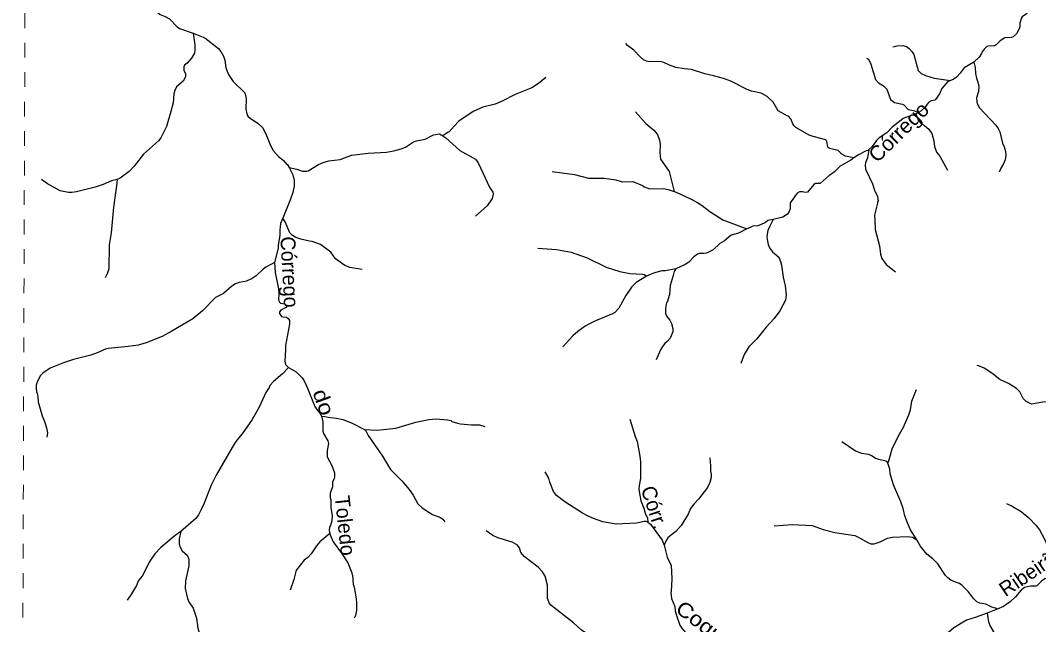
# Model space of a CAD drawing. Extents: x 551.6 to 577.6, y 7567 to 7594.7.
# Drawn here: x 551.65 to 558.55, y 7583.85 to 7587.95 of the extents above; entities that cross this region are included whole.
import ezdxf
from ezdxf.enums import TextEntityAlignment as Align

# ---------------------------------------------------------------- set-up
doc = ezdxf.new("R2010")
doc.units = 0
doc.header["$LTSCALE"] = 0.04
doc.linetypes.add('SHORT_DASHED', pattern=[2.7, 1.5, -1.2])
doc.layers.add('53', color=7, linetype='SHORT_DASHED', lineweight=13)
doc.layers.add('7', color=7, linetype='Continuous', lineweight=25)
doc.layers.add('61', color=7, linetype='Continuous')

msp = doc.modelspace()

# ---------------------------------------------------------------- linework, layer by layer
at = {"layer": '53'}
msp.add_lwpolyline([(551.6503, 7578.541), (551.6589, 7581.176), (551.6615, 7581.9586), (551.6634, 7582.5573), (551.6645, 7582.8996), (551.6852, 7589.2613), (551.6863, 7589.5882), (551.6896, 7590.6141), (551.6917, 7591.2598), (551.6958, 7592.5139), (551.6971, 7592.9033), (551.701, 7594.113), (551.703, 7594.7296), (552.7903, 7594.7256), (553.4424, 7594.7233), (554.6279, 7594.7189), (556.5859, 7594.7118), (557.3702, 7594.7089), (557.7663, 7594.7075), (559.9893, 7594.6994)], dxfattribs=at)
at = {"layer": '7'}
for points in [[(552.32, 7588.3987), (552.3168, 7588.3536), (552.3265, 7588.3198), (552.3466, 7588.2763), (552.3828, 7588.2385), (552.4367, 7588.2063), (552.4874, 7588.1652), (552.4939, 7588.1492), (552.5019, 7588.0928), (552.5075, 7588.0816), (552.5679, 7588.0172), (552.5969, 7587.9906), (552.6323, 7587.9777), (552.6605, 7587.9624), (552.712, 7587.9069), (552.7289, 7587.8964), (552.8218, 7587.8654)], [(558.4947, 7588.043), (558.4711, 7587.9954), (558.4397, 7587.9745), (558.4365, 7587.9689), (558.4252, 7587.9335), (558.4252, 7587.9077), (558.4212, 7587.8949), (558.4019, 7587.8602), (558.3802, 7587.8393), (558.3673, 7587.8353), (558.3222, 7587.8337), (558.2917, 7587.8119), (558.2651, 7587.7846), (558.253, 7587.7781), (558.245, 7587.7757), (558.2208, 7587.7789), (558.2023, 7587.7733), (558.183, 7587.7564), (558.1693, 7587.7387), (558.1661, 7587.7266), (558.1484, 7587.7017), (558.1123, 7587.6688)], [(552.8218, 7587.8654), (552.8335, 7587.7854), (552.8335, 7587.7516), (552.8295, 7587.7291), (552.811, 7587.6953), (552.782, 7587.6614), (552.7635, 7587.647), (552.7594, 7587.6373), (552.7578, 7587.6132), (552.7691, 7587.5882), (552.7691, 7587.5713), (552.7651, 7587.5601), (552.753, 7587.5399), (552.7096, 7587.5013), (552.6967, 7587.4747), (552.691, 7587.4538), (552.6854, 7587.3927), (552.6709, 7587.3331), (552.6403, 7587.2317), (552.6017, 7587.1544), (552.5872, 7587.1335), (552.4858, 7587.0434)], [(552.8218, 7587.8654), (552.9003, 7587.8329), (552.9928, 7587.7613), (553.0097, 7587.7403), (553.0283, 7587.7097), (553.0363, 7587.6808)], [(556.7118, 7587.4345), (556.6724, 7587.457), (556.6064, 7587.4723), (556.5774, 7587.4836), (556.4656, 7587.5399), (556.4165, 7587.5568), (556.3489, 7587.5761), (556.2893, 7587.589), (556.2, 7587.618), (556.1493, 7587.622), (556.093, 7587.6325), (556.0511, 7587.647), (556.0125, 7587.6663), (555.9932, 7587.6711), (555.961, 7587.6735), (555.9159, 7587.6703), (555.8934, 7587.6743), (555.8732, 7587.6848), (555.8507, 7587.7033), (555.8088, 7587.7492), (555.7654, 7587.7814), (555.7541, 7587.7942)], [(557.5633, 7587.7709), (557.5915, 7587.7798), (557.6317, 7587.7814), (557.6559, 7587.7741), (557.6744, 7587.7596), (557.6929, 7587.7403), (557.7058, 7587.721), (557.7363, 7587.6124), (557.7557, 7587.5906), (557.7863, 7587.5777), (557.8442, 7587.56), (557.955, 7587.5435)], [(553.0363, 7587.6808), (553.0435, 7587.6293), (553.0605, 7587.5842), (553.0935, 7587.5359), (553.1723, 7587.4603), (553.1812, 7587.4216), (553.178, 7587.3492), (553.1844, 7587.3178), (553.1932, 7587.3025), (553.2102, 7587.2856), (553.26, 7587.2542), (553.2906, 7587.2236), (553.3148, 7587.1818), (553.3453, 7587.1029), (553.3639, 7587.0675), (553.4009, 7587.0273), (553.4347, 7587.0007), (553.4548, 7586.9766), (553.458, 7586.9766), (553.4731, 7586.9537)], [(557.3863, 7587.6945), (557.3983, 7587.688), (557.4144, 7587.655), (557.4466, 7587.5504), (557.4676, 7587.5278), (557.5013, 7587.5077), (557.5223, 7587.4844), (557.548, 7587.4136), (557.5746, 7587.395), (557.6293, 7587.3822), (557.639, 7587.3774), (557.6671, 7587.346), (557.7042, 7587.3395), (557.7372, 7587.3264)], [(558.1123, 7587.6688), (558.0486, 7587.6293), (558.0204, 7587.5922), (557.9955, 7587.5665), (557.973, 7587.5512), (557.955, 7587.5435)], [(558.1123, 7587.6688), (558.121, 7587.6309), (558.1243, 7587.5906), (558.1307, 7587.5584), (558.1428, 7587.5263), (558.1468, 7587.5021), (558.1436, 7587.4699), (558.1307, 7587.4265), (558.1331, 7587.3975), (558.1403, 7587.3782), (558.1524, 7587.3589), (558.2627, 7587.2413), (558.2788, 7587.2188), (558.2884, 7587.1947), (558.3069, 7587.1174), (558.3182, 7587.0933), (558.3279, 7587.0611), (558.3295, 7587.0369), (558.3255, 7587.0047), (558.3118, 7586.9725), (558.2965, 7586.9484), (558.2844, 7586.9218)], [(555.2123, 7587.5628), (555.1634, 7587.5222), (555.1175, 7587.494), (555.0049, 7587.4482), (554.9163, 7587.4031), (554.8697, 7587.383), (554.7859, 7587.3625), (554.7184, 7587.3323), (554.6234, 7587.2671), (554.5896, 7587.2341), (554.5574, 7587.1955), (554.5509, 7587.1938), (554.5142, 7587.1679)], [(557.955, 7587.5435), (557.9375, 7587.5359), (557.8973, 7587.4892), (557.8804, 7587.4522), (557.8539, 7587.4136), (557.8482, 7587.4095), (557.8249, 7587.4055), (557.8088, 7587.3967), (557.7959, 7587.383), (557.7838, 7587.3637), (557.7541, 7587.3363), (557.7372, 7587.3264), (557.7208, 7587.3169)], [(557.2987, 7587.0181), (557.2422, 7587.0305), (557.2148, 7587.045), (557.2148, 7587.0482), (557.1939, 7587.0683), (557.1344, 7587.0812), (557.1231, 7587.0909), (557.1166, 7587.1327), (557.107, 7587.1399), (557.0861, 7587.148), (557.0233, 7587.1625), (556.9976, 7587.1729), (556.9058, 7587.2252), (556.8961, 7587.2349), (556.8873, 7587.2502), (556.8728, 7587.2832), (556.8567, 7587.3025), (556.8487, 7587.3033), (556.7867, 7587.3379), (556.7521, 7587.3959), (556.7118, 7587.4345)], [(555.8201, 7587.3307), (555.8893, 7587.251), (555.9441, 7587.2067), (555.969, 7587.177), (555.9819, 7587.1383), (555.9867, 7587.1094), (555.9851, 7587.0546), (555.9899, 7587.0096), (556.0479, 7586.9259), (556.0821, 7586.79)], [(557.7208, 7587.3169), (557.635, 7587.2848), (557.6197, 7587.2751), (557.5593, 7587.2277), (557.5223, 7587.189), (557.4708, 7587.1552), (557.4539, 7587.1367), (557.4249, 7587.0949), (557.4024, 7587.0758)], [(557.7208, 7587.3169), (557.7315, 7587.2864), (557.7404, 7587.2711), (557.7524, 7587.2574), (557.779, 7587.2389), (557.8072, 7587.2132), (557.8281, 7587.1834), (557.841, 7587.1351), (557.8466, 7587.0965), (557.8611, 7587.0579), (557.882, 7587.0297), (557.9351, 7586.9347)], [(553.4731, 7586.9537), (553.524, 7586.9428), (553.5627, 7586.9291), (553.5916, 7586.9275), (553.6013, 7586.9299), (553.6705, 7586.9725), (553.7027, 7586.987), (553.7413, 7586.9991), (553.8186, 7587.0079), (553.8959, 7587.0369), (554.0069, 7587.0514), (554.1325, 7587.0578), (554.1808, 7587.0659), (554.2323, 7587.0788), (554.2604, 7587.0916), (554.316, 7587.1271), (554.3353, 7587.1343), (554.3932, 7587.1464), (554.4496, 7587.1753)], [(554.4496, 7587.1753), (554.4914, 7587.1818), (554.5142, 7587.1679)], [(554.5142, 7587.1679), (554.5349, 7587.1536), (554.6298, 7587.0691), (554.7361, 7587.0096), (554.7537, 7586.9838), (554.8302, 7586.8196), (554.8536, 7586.785), (554.856, 7586.7714), (554.8487, 7586.7424), (554.8149, 7586.6941), (554.7353, 7586.6241)], [(557.3839, 7587.0667), (557.3315, 7587.0401), (557.2987, 7587.0181)], [(557.4024, 7587.0758), (557.3919, 7587.0192), (557.3798, 7586.9854), (557.3774, 7586.9709), (557.379, 7586.9428), (557.4257, 7586.8422), (557.4394, 7586.8003), (557.4611, 7586.7553), (557.4643, 7586.7247), (557.4611, 7586.7215), (557.4611, 7586.7102), (557.4402, 7586.6305), (557.441, 7586.5949), (557.445, 7586.5315), (557.4748, 7586.4221), (557.4796, 7586.3641), (557.4893, 7586.3352), (557.5191, 7586.2941), (557.581, 7586.2442)], [(557.4024, 7587.0758), (557.3935, 7587.0683), (557.3839, 7587.0667)], [(552.4858, 7587.0434), (552.4206, 7586.9613), (552.3877, 7586.9258), (552.3273, 7586.8808), (552.3059, 7586.8725)], [(557.2987, 7587.0181), (557.2792, 7587.0023), (557.2068, 7586.9629), (557.1682, 7586.9234), (557.1448, 7586.9049), (557.1319, 7586.8993), (557.0708, 7586.8438), (557.0394, 7586.8438), (557.0289, 7586.8381), (556.9863, 7586.7866), (556.9702, 7586.7842), (556.9509, 7586.789), (556.9316, 7586.789), (556.9146, 7586.7786), (556.8672, 7586.7134), (556.8688, 7586.6732), (556.8615, 7586.6539), (556.8503, 7586.6361), (556.8189, 7586.6152), (556.7524, 7586.6004)], [(553.4731, 7586.9537), (553.4967, 7586.9033), (553.5063, 7586.8647), (553.5063, 7586.8261), (553.4967, 7586.7842), (553.4814, 7586.7392), (553.4294, 7586.6101)], [(555.2552, 7586.9259), (555.4073, 7586.9065), (555.5006, 7586.8816), (555.6085, 7586.8808), (555.6857, 7586.8695), (555.7292, 7586.855), (555.8016, 7586.8583), (555.8668, 7586.8301), (555.8789, 7586.822), (555.9175, 7586.8084), (556.0093, 7586.81), (556.0414, 7586.8035), (556.0821, 7586.79), (556.0946, 7586.7858)], [(552.3059, 7586.8725), (552.2685, 7586.8631), (552.2122, 7586.8381), (552.1575, 7586.8196), (552.0319, 7586.7874), (551.9997, 7586.7826), (551.9756, 7586.7842), (551.9209, 7586.7955), (551.834, 7586.8413), (551.7945, 7586.8711)], [(552.3059, 7586.8725), (552.3023, 7586.8277), (552.2814, 7586.6844), (552.2653, 7586.509), (552.2524, 7586.4285), (552.2492, 7586.2659), (552.2396, 7586.2321), (552.2251, 7586.2056)], [(556.0946, 7586.7858), (556.1976, 7586.7391), (556.2362, 7586.7182), (556.2716, 7586.6957), (556.3247, 7586.6538), (556.4117, 7586.5983), (556.5741, 7586.5376)], [(553.4294, 7586.6101), (553.4146, 7586.5734), (553.4081, 7586.5283), (553.4097, 7586.4929), (553.3977, 7586.4253), (553.3969, 7586.406), (553.3731, 7586.3081)], [(553.9675, 7586.2603), (553.883, 7586.274), (553.8492, 7586.2885), (553.7872, 7586.3335), (553.7542, 7586.3786), (553.685, 7586.4317), (553.6287, 7586.451), (553.6093, 7586.4526), (553.5514, 7586.4671), (553.5176, 7586.4784), (553.4951, 7586.4913), (553.4773, 7586.5106), (553.4443, 7586.5846), (553.4294, 7586.6101)], [(556.7524, 7586.6004), (556.7271, 7586.5508), (556.7175, 7586.5251), (556.711, 7586.4881), (556.7118, 7586.4655), (556.7191, 7586.4317), (556.7287, 7586.4076), (556.748, 7586.381), (556.7915, 7586.344), (556.8028, 7586.3158), (556.8092, 7586.2901), (556.8205, 7586.208), (556.8334, 7586.15), (556.8414, 7586.0873), (556.8374, 7586.0535), (556.7971, 7585.981), (556.7601, 7585.9279), (556.7062, 7585.87), (556.6418, 7585.7911), (556.5879, 7585.7364), (556.5565, 7585.6849), (556.5348, 7585.6229)], [(556.7524, 7586.6004), (556.7175, 7586.5927), (556.7014, 7586.5806), (556.6676, 7586.5637), (556.6483, 7586.5573), (556.6145, 7586.5556), (556.5935, 7586.5436), (556.5741, 7586.5376)], [(556.5741, 7586.5376), (556.5179, 7586.5082), (556.4688, 7586.4945), (556.4221, 7586.455), (556.3923, 7586.4373), (556.3457, 7586.3947), (556.3006, 7586.373), (556.2829, 7586.3689), (556.2523, 7586.3705), (556.241, 7586.3657), (556.2161, 7586.3472), (556.1815, 7586.311), (556.1565, 7586.2941), (556.093, 7586.2659)], [(555.157, 7586.406), (555.2833, 7586.3963), (555.3847, 7586.3786), (555.4926, 7586.3408), (555.6213, 7586.278), (555.7147, 7586.2482), (555.7823, 7586.2337), (555.8676, 7586.2305), (555.8811, 7586.2277), (555.8933, 7586.2168)], [(553.3731, 7586.3081), (553.3148, 7586.2772), (553.2955, 7586.2627), (553.2488, 7586.2184), (553.2206, 7586.1999), (553.1828, 7586.1822), (553.1345, 7586.1726), (553.1095, 7586.1637), (553.083, 7586.1484), (553.0267, 7586.0993), (552.9727, 7586.072), (552.885, 7585.981), (552.8198, 7585.9271), (552.782, 7585.903), (552.6774, 7585.8418), (552.6106, 7585.8072), (552.5019, 7585.7637), (552.4488, 7585.7484)], [(553.3731, 7586.3081), (553.3775, 7586.2402), (553.4009, 7586.1307), (553.4025, 7586.0937), (553.3993, 7586.0583), (553.4017, 7586.0486), (553.4065, 7586.039), (553.4146, 7586.0333), (553.4436, 7586.0285), (553.458, 7586.0148), (553.4508, 7586.0027), (553.4162, 7585.985), (553.4065, 7585.9738), (553.4065, 7585.9617)], [(556.093, 7586.2659), (556.0237, 7586.253), (555.998, 7586.2514), (555.9417, 7586.2361), (555.8933, 7586.2168)], [(556.093, 7586.2659), (556.0817, 7586.2474), (556.076, 7586.2193), (556.0543, 7586.1517), (556.0495, 7586.0905), (556.0334, 7586.039), (556.0302, 7586.0374), (556.0221, 7585.9955), (556.0221, 7585.9617), (556.0318, 7585.9432), (556.0527, 7585.9167), (556.064, 7585.8941), (556.072, 7585.8603), (556.072, 7585.8378), (556.0551, 7585.7943), (556.035, 7585.7726), (556.0181, 7585.7597), (556.0028, 7585.7396), (555.9899, 7585.7171), (555.961, 7585.647)], [(555.8933, 7586.2168), (555.8242, 7586.1734), (555.7936, 7586.1404), (555.7541, 7586.0841), (555.7074, 7585.9979), (555.6793, 7585.9689), (555.6632, 7585.9593), (555.5489, 7585.9126), (555.5071, 7585.8917), (555.4797, 7585.8756), (555.4298, 7585.8394)], [(553.4065, 7585.9617), (553.4194, 7585.9432), (553.4291, 7585.9392), (553.4548, 7585.9376), (553.4644, 7585.9295), (553.4741, 7585.915), (553.4741, 7585.8909), (553.4476, 7585.746), (553.4484, 7585.7171), (553.4419, 7585.6366), (553.4484, 7585.6157), (553.467, 7585.5956)], [(555.4298, 7585.8394), (555.396, 7585.812), (555.3276, 7585.7364)], [(552.4488, 7585.7484), (552.3812, 7585.738), (552.246, 7585.7243), (552.2267, 7585.7195), (552.172, 7585.6961), (552.1269, 7585.6808), (552.0094, 7585.6502), (551.9418, 7585.6277), (551.8517, 7585.5915), (551.8018, 7585.5585), (551.7865, 7585.5424), (551.7631, 7585.4982), (551.7567, 7585.4756), (551.7567, 7585.4467), (551.7599, 7585.4418), (551.7599, 7585.4265), (551.7631, 7585.4241), (551.7679, 7585.3968), (551.7712, 7585.363), (551.7985, 7585.268), (551.8146, 7585.2294), (551.8275, 7585.1859)], [(558.5041, 7585.3484), (558.4671, 7585.3646), (558.4486, 7585.3855), (558.4244, 7585.4306), (558.4019, 7585.4539), (558.3488, 7585.4885), (558.2892, 7585.5158), (558.2361, 7585.5577), (558.1838, 7585.5907), (558.1516, 7585.6052), (558.1347, 7585.6092)], [(553.467, 7585.5956), (553.4266, 7585.5521), (553.3663, 7585.5005), (553.3421, 7585.474), (553.3365, 7585.4603), (553.3148, 7585.4273), (553.2689, 7585.3259), (553.2214, 7585.2438), (553.1538, 7585.1456), (553.1168, 7585.1022), (553.1023, 7585.0797), (552.9784, 7584.8656), (552.9446, 7584.798), (552.8963, 7584.6757), (552.8761, 7584.6322), (552.8576, 7584.596), (552.8391, 7584.571), (552.7391, 7584.4841)], [(553.467, 7585.5956), (553.5208, 7585.5674), (553.5602, 7585.5255), (553.5739, 7585.5046), (553.5972, 7585.4563), (553.6471, 7585.3308), (553.6592, 7585.3114)], [(557.5299, 7584.9476), (557.5371, 7584.9629), (557.5593, 7585.0443), (557.5995, 7585.128), (557.6357, 7585.1923), (557.6728, 7585.276), (557.6832, 7585.3098), (557.6937, 7585.3678), (557.7251, 7585.4458)], [(559.4867, 7584.9721), (559.4715, 7584.9774), (559.4425, 7584.9798), (559.42, 7584.9879), (559.3991, 7585.0048), (559.3572, 7585.0281), (559.2952, 7585.045), (559.2462, 7585.0652), (559.2276, 7585.0813), (559.189, 7585.1239), (559.1641, 7585.144), (559.111, 7585.173), (559.0997, 7585.1746), (559.0659, 7585.1891), (559.0256, 7585.2165), (559.0192, 7585.2165), (558.9436, 7585.2559), (558.8325, 7585.28), (558.7222, 7585.3291), (558.624, 7585.3629), (558.5798, 7585.3613), (558.5041, 7585.3484)], [(553.6592, 7585.3114), (553.6802, 7585.2865), (553.6914, 7585.2648)], [(553.6914, 7585.2648), (553.6995, 7585.2277), (553.7011, 7585.1634), (553.7059, 7585.1473), (553.7341, 7585.099), (553.7397, 7585.0813), (553.73, 7585.033), (553.73, 7584.9895), (553.7606, 7584.9316), (553.7791, 7584.8817), (553.7799, 7584.8567), (553.7767, 7584.8414), (553.7663, 7584.8205), (553.7655, 7584.7867), (553.7502, 7584.7433), (553.7494, 7584.7143), (553.7542, 7584.6982), (553.755, 7584.6451)], [(553.6914, 7585.2648), (553.714, 7585.2647), (553.7365, 7585.2583), (553.7928, 7585.2519), (553.8363, 7585.2422), (553.8942, 7585.2197), (553.9821, 7585.1745)], [(551.8275, 7585.1859), (551.8339, 7585.1521), (551.8307, 7585.1223)], [(553.9821, 7585.1745), (554.0681, 7585.1714), (554.1952, 7585.1843), (554.3304, 7585.2245), (554.419, 7585.2438), (554.4689, 7585.247), (554.5461, 7585.2414), (554.5687, 7585.2358), (554.5751, 7585.2301), (554.6137, 7585.2173), (554.633, 7585.2133), (554.7071, 7585.206), (554.7634, 7585.206), (554.7996, 7585.1956)], [(555.7823, 7585.2463), (555.8177, 7585.128), (555.8306, 7585.0941), (555.8499, 7584.9944), (555.8547, 7584.9557), (555.8547, 7584.8801), (555.8531, 7584.8431), (555.8442, 7584.7948), (555.8434, 7584.769), (555.8555, 7584.6917), (555.8773, 7584.6419), (555.8861, 7584.6081), (555.9006, 7584.5742), (555.9036, 7584.5466)], [(553.9821, 7585.1745), (553.9892, 7585.1698), (554.0085, 7585.1344), (554.1043, 7584.9944), (554.159, 7584.905), (554.2355, 7584.8261), (554.2853, 7584.7682), (554.3127, 7584.7288), (554.3449, 7584.6716), (554.3747, 7584.6434), (554.419, 7584.6137)], [(557.2173, 7585.0933), (557.3114, 7585.0297), (557.3517, 7585.0153), (557.4, 7585.0072), (557.4249, 7584.9968), (557.4474, 7584.9806), (557.4659, 7584.9734), (557.5094, 7584.9654), (557.5191, 7584.9605), (557.5299, 7584.9476)], [(556.3231, 7584.9823), (556.3287, 7584.9284), (556.3287, 7584.8946), (556.3328, 7584.872), (556.332, 7584.8495), (556.3231, 7584.8157), (556.3078, 7584.7819), (556.2467, 7584.7022), (556.2153, 7584.6692), (556.1927, 7584.6386), (556.1758, 7584.6016), (556.1291, 7584.5244), (556.0929, 7584.4833), (556.0543, 7584.4543), (556.0398, 7584.4398), (556.0261, 7584.4181), (556.0137, 7584.3899)], [(557.6172, 7584.6837), (557.5689, 7584.7996), (557.5456, 7584.8736), (557.5432, 7584.9058), (557.5299, 7584.9476)], [(555.9036, 7584.5466), (555.8942, 7584.5509), (555.8789, 7584.5517), (555.8274, 7584.5404), (555.6889, 7584.534), (555.5988, 7584.5493), (555.5344, 7584.571), (555.499, 7584.5871), (555.4596, 7584.6088), (555.3397, 7584.6853), (555.2849, 7584.7271), (555.2648, 7584.7545), (555.2398, 7584.8189), (555.2334, 7584.8447), (555.2085, 7584.8889)], [(553.755, 7584.6451), (553.7638, 7584.5903), (553.7614, 7584.5565), (553.7494, 7584.5163), (553.7461, 7584.5139), (553.7445, 7584.4905), (553.7479, 7584.469)], [(557.7267, 7584.4278), (557.6848, 7584.4938), (557.6631, 7584.5421), (557.6462, 7584.5903), (557.6349, 7584.6386), (557.6172, 7584.6837)], [(558.3343, 7584.6724), (558.3738, 7584.6563), (558.4349, 7584.6201), (558.4856, 7584.5759), (558.5363, 7584.5243), (558.5588, 7584.4954), (558.5943, 7584.4278), (558.6192, 7584.3698), (558.6474, 7584.3215), (558.6723, 7584.2942), (558.7037, 7584.2748), (558.7194, 7584.2696)], [(554.419, 7584.6137), (554.4431, 7584.5984), (554.4978, 7584.5774), (554.5131, 7584.5662), (554.5276, 7584.5493)], [(555.9036, 7584.5466), (555.9207, 7584.5332), (555.9996, 7584.4245), (556.0137, 7584.3899)], [(556.7601, 7584.5227), (556.8817, 7584.53), (557.0169, 7584.5235), (557.0909, 7584.4978), (557.1714, 7584.476), (557.3066, 7584.4551), (557.3388, 7584.4398), (557.3935, 7584.4076), (557.416, 7584.4004), (557.4386, 7584.4004), (557.4772, 7584.4133), (557.5287, 7584.4374), (557.5625, 7584.4439), (557.6639, 7584.4503), (557.6977, 7584.4455), (557.7267, 7584.4278)], [(552.7391, 7584.4841), (552.7007, 7584.4567), (552.6025, 7584.3754), (552.5615, 7584.3312), (552.5236, 7584.2749), (552.4923, 7584.2089), (552.4754, 7584.1799), (552.4504, 7584.1509), (552.4367, 7584.1171), (552.4045, 7584.0608), (552.3748, 7584.0181)], [(552.7391, 7584.4841), (552.7273, 7584.4326), (552.7273, 7584.3988), (552.7337, 7584.3763), (552.7466, 7584.3529), (552.7804, 7584.3232), (552.7933, 7584.2958), (552.7933, 7584.2507), (552.7691, 7584.1493), (552.7667, 7584.0962), (552.7836, 7584.0286), (552.7933, 7584.0061), (552.8222, 7583.9626), (552.8448, 7583.895), (552.8528, 7583.8274), (552.8689, 7583.7711), (552.8802, 7583.7139)], [(553.7479, 7584.469), (553.681, 7584.4133), (553.6584, 7584.3859), (553.6214, 7584.3312), (553.5981, 7584.3078), (553.5739, 7584.2893), (553.5224, 7584.2241), (553.5168, 7584.2121), (553.5047, 7584.1581), (553.479, 7584.0841)], [(553.7479, 7584.469), (553.7493, 7584.46), (553.7703, 7584.4125), (553.8274, 7584.3368), (553.8693, 7584.27), (553.8966, 7584.2024), (553.8982, 7584.1879), (553.9007, 7584.1871), (553.9071, 7584.1252), (553.9135, 7584.1059), (553.9272, 7584.0254), (553.9288, 7583.9996), (553.928, 7583.9465), (553.9216, 7583.9127), (553.9136, 7583.8942)], [(555.2238, 7584.1187), (555.2068, 7584.1799), (555.1891, 7584.2089), (555.1602, 7584.2411), (555.0644, 7584.3143), (555.0419, 7584.3417), (555.033, 7584.3714), (555.0185, 7584.3932), (554.9839, 7584.4117), (554.8858, 7584.4414), (554.852, 7584.4559), (554.8077, 7584.4881)], [(558.2723, 7583.9567), (558.2595, 7583.9634), (558.2353, 7583.9698), (558.1951, 7583.9891), (558.1532, 7583.9972), (558.1331, 7584.006), (558.1122, 7584.0254), (558.0752, 7584.0753), (558.0341, 7584.1171), (558.0164, 7584.13), (557.9955, 7584.1364), (557.9577, 7584.1541), (557.9375, 7584.1678), (557.9206, 7584.1855), (557.8699, 7584.2628), (557.8353, 7584.2974), (557.7951, 7584.3304), (557.7484, 7584.3867), (557.7267, 7584.4278)], [(556.0137, 7584.3899), (556.035, 7584.3087), (556.0535, 7584.2708)], [(556.0535, 7584.2708), (556.0607, 7584.2547), (556.0656, 7584.1622), (556.0624, 7584.0761), (556.0591, 7584.0688), (556.064, 7584.0286), (556.0865, 7583.9739), (556.0897, 7583.9449), (556.0994, 7583.9063), (556.1211, 7583.8483), (556.134, 7583.8266), (556.1565, 7583.7992), (556.1801, 7583.78)], [(558.7194, 7584.2696), (558.7182, 7584.2491), (558.7094, 7584.2314), (558.7037, 7584.2322), (558.6925, 7584.2467), (558.6707, 7584.2475), (558.6651, 7584.2298), (558.6723, 7584.1928), (558.6578, 7584.1734), (558.5951, 7584.1614), (558.5725, 7584.1453), (558.5395, 7584.1139), (558.5331, 7584.1115), (558.4961, 7584.1123), (558.4575, 7584.1026), (558.4349, 7584.0857), (558.3955, 7584.0398), (558.3593, 7584.0052), (558.3142, 7583.9754), (558.2723, 7583.9567), (558.204, 7583.9281), (558.1211, 7583.8998)], [(555.5411, 7583.7827), (555.5119, 7583.7815), (555.4942, 7583.7871), (555.4507, 7583.8169), (555.4, 7583.8628), (555.2455, 7583.9843), (555.2366, 7583.9948), (555.2238, 7584.0286), (555.2238, 7584.1187)], [(558.1211, 7583.8998), (558.0639, 7583.8813), (557.9778, 7583.829), (557.9424, 7583.7984), (557.9215, 7583.7847), (557.8619, 7583.7606), (557.8386, 7583.7445), (557.8128, 7583.7212), (557.779, 7583.6696), (557.7527, 7583.6485)], [(558.204, 7583.9281), (558.2128, 7583.8692), (558.224, 7583.8403), (558.319, 7583.6793), (558.3681, 7583.5731), (558.3858, 7583.5449), (558.4631, 7583.4572), (558.5138, 7583.3606), (558.5331, 7583.3123), (558.5613, 7583.2206), (558.5943, 7583.0081), (558.6063, 7582.9663), (558.6192, 7582.9373)]]:
    msp.add_lwpolyline(points, dxfattribs=at)

# ---------------------------------------------------------------- texts
at = {"layer": '61'}
for s, rotation, width, p in [('Córrego', 44.625, 1.05, (557.6389, 7587.1582)), ('do', 289.679, 1.2, (553.6595, 7585.3445)), ('Coqueri', 322.641, 1.15, (556.2965, 7583.7795))]:
    msp.add_text(s, height=0.1, rotation=rotation, dxfattribs=dict(at, width=width)).set_placement(p, align=Align.CENTER)
for s, rotation, p in [('Córrego', 273.062, (553.4256, 7586.2418)), ('Córr.', 288.201, (555.901, 7584.6317)), ('Toledo', 275.949, (553.8029, 7584.5186)), ('Ribeirão', 33.919, (558.534, 7584.1751))]:
    msp.add_text(s, height=0.1, rotation=rotation, dxfattribs=at).set_placement(p, align=Align.CENTER)

doc.saveas('drawing.dxf')
